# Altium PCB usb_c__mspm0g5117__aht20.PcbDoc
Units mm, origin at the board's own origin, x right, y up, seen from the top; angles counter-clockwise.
Board outline 92 x 60 mm, 2 copper layers (Top, Bottom), stack 0 mm thick; 36 components, 31 nets, 180 pads, 56 vias.
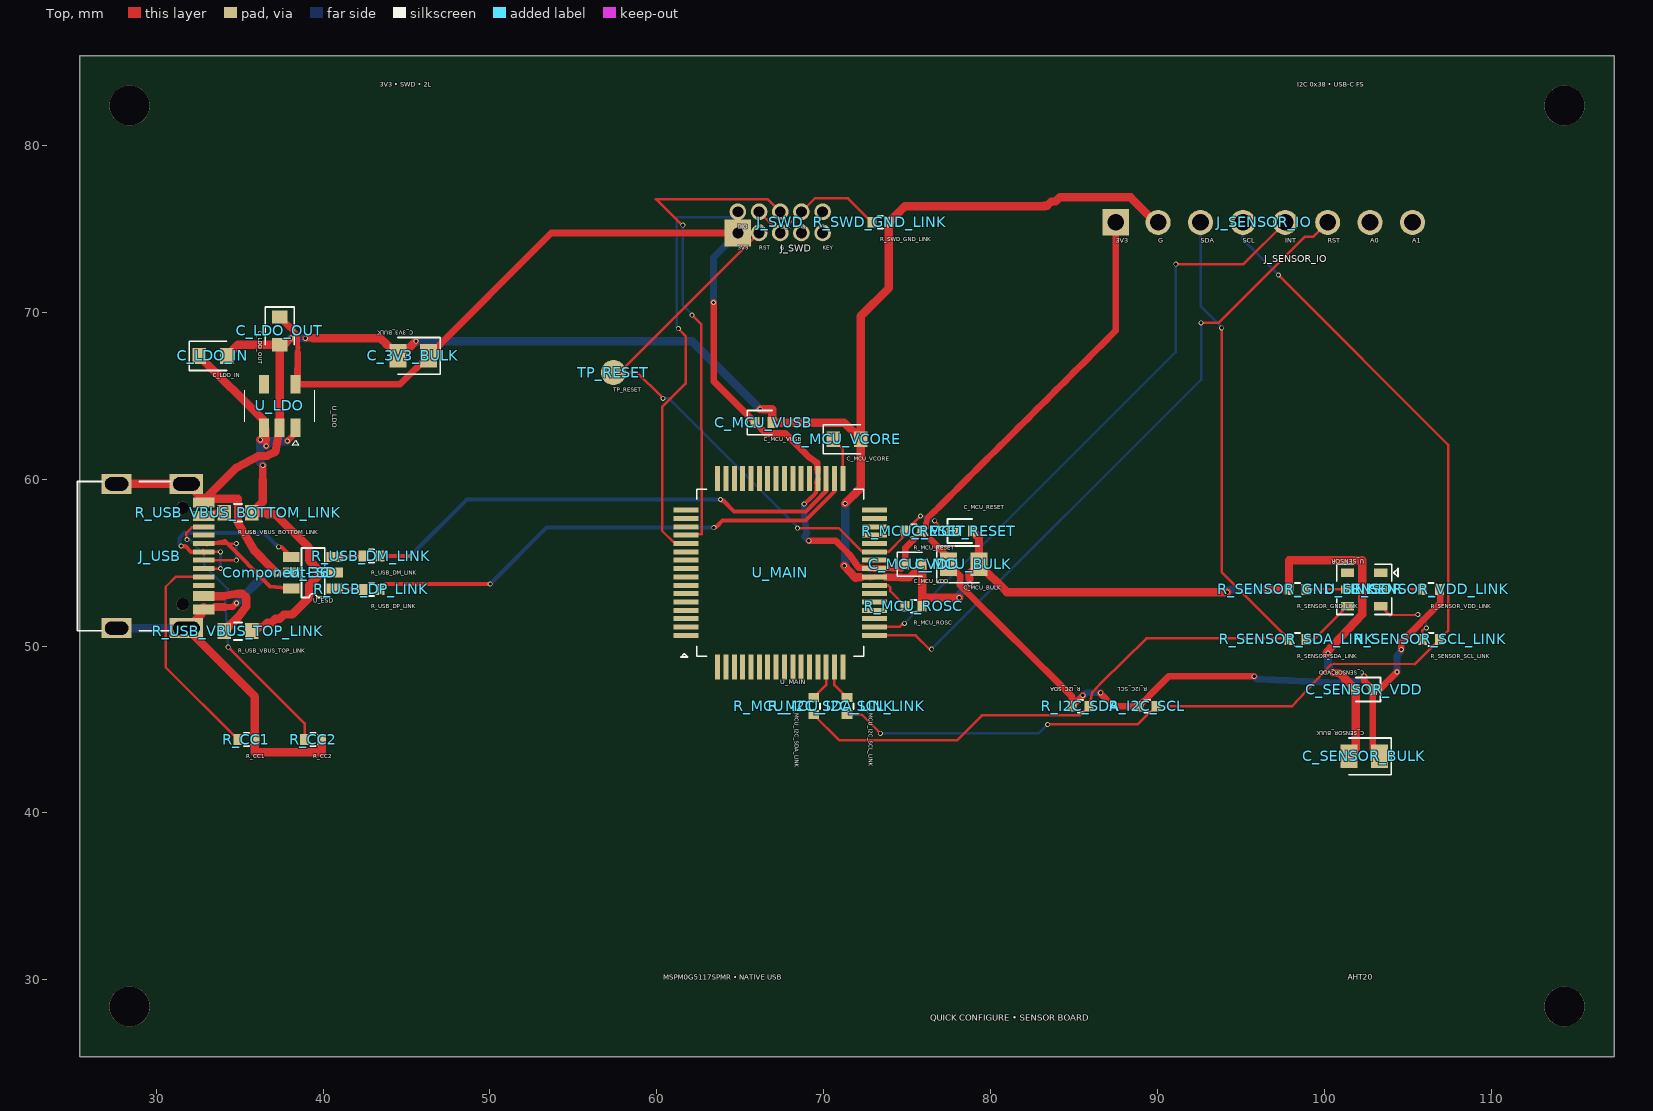
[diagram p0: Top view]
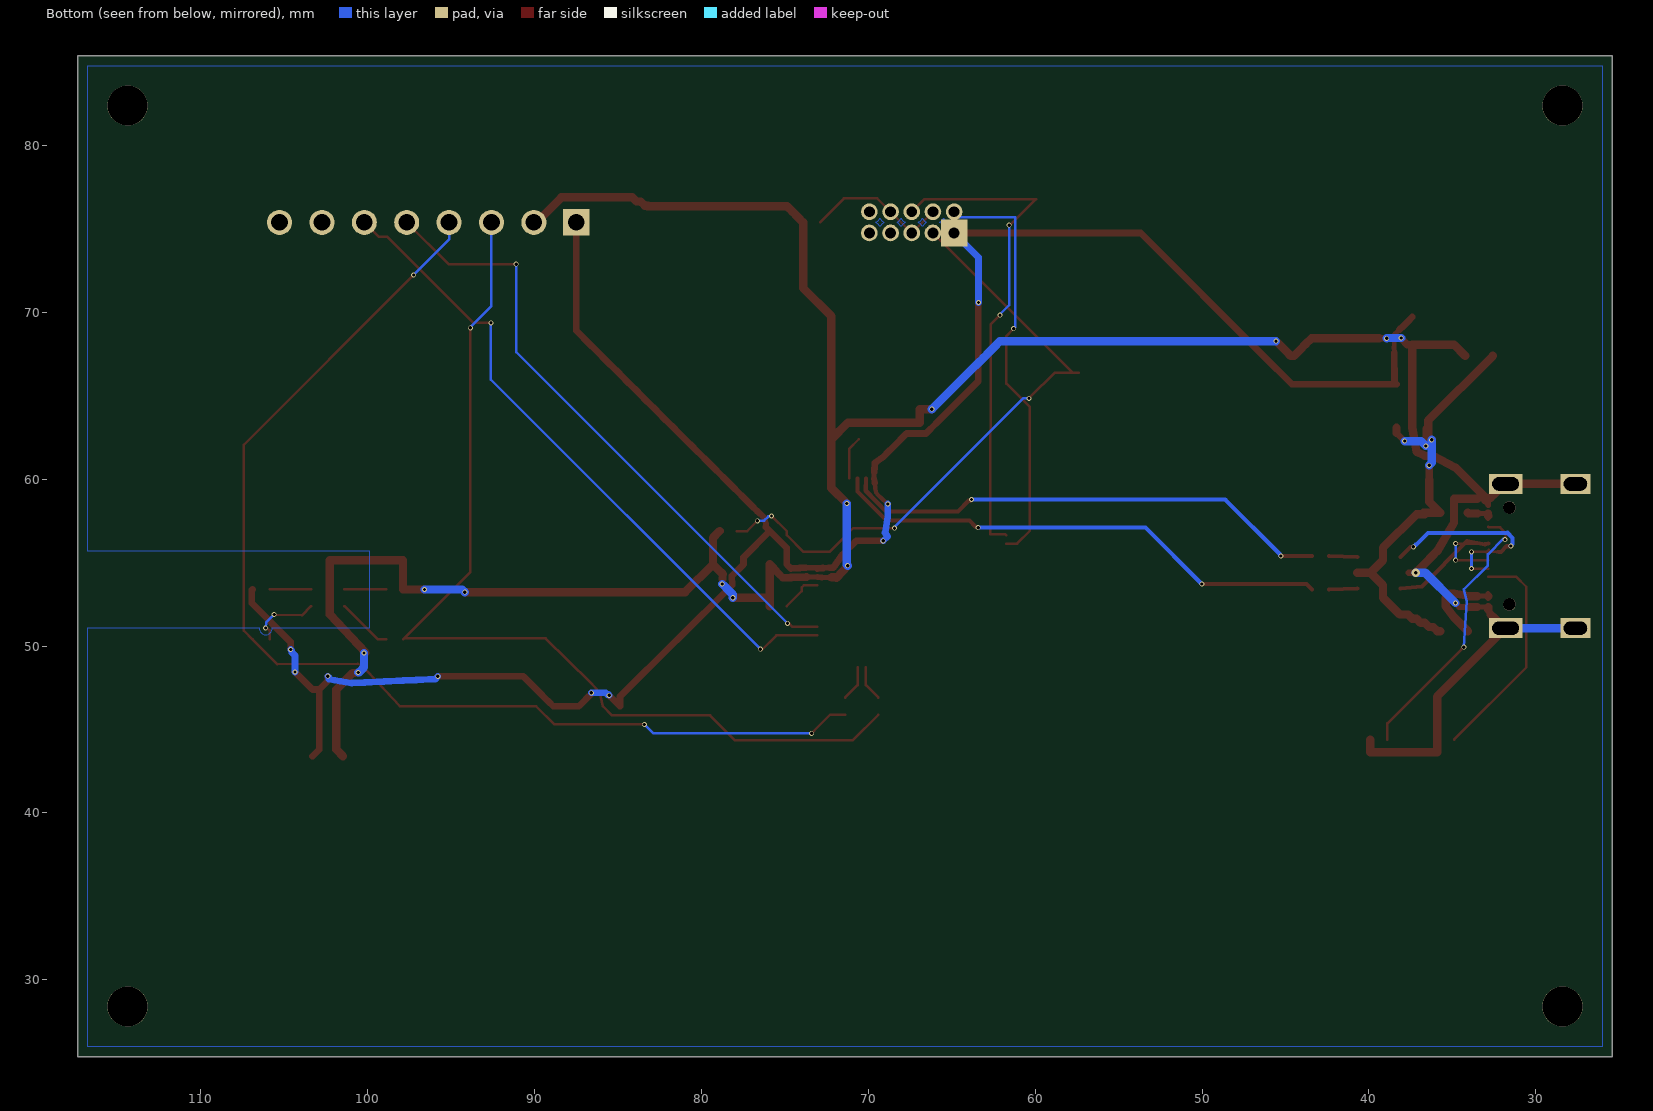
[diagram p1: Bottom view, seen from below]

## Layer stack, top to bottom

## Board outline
25.4,85.4 117.4,85.4 117.4,25.4 25.4,25.4

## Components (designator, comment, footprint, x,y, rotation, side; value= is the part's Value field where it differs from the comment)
C_3V3_BULK "" TSCIRCUIT-2.8500x1.4000mm 45.4,67.4 r180 top
C_LDO_IN "" TSCIRCUIT-2.4500x0.9500mm 33.4,67.4 r0 top
C_LDO_OUT "" TSCIRCUIT-0.9500x2.4500mm 37.4,68.9 r270 top
C_MCU_BULK "" TSCIRCUIT-2.8500x1.4000mm 78.4,54.9 r0 top
C_MCU_RESET "" TSCIRCUIT-1.5600x0.6400mm 78.4,56.9 r0 top
C_MCU_VCORE "" TSCIRCUIT-2.4500x0.9500mm 71.4,62.4 r0 top
C_MCU_VDD "" TSCIRCUIT-1.5600x0.6400mm 75.4,54.9 r0 top
C_MCU_VUSB "" TSCIRCUIT-1.5600x0.6400mm 66.4,63.4 r0 top
C_SENSOR_BULK "" TSCIRCUIT-2.8500x1.4000mm 102.4,43.4 r180 top
C_SENSOR_VDD "" TSCIRCUIT-1.5600x0.6400mm 102.4,47.4 r180 top
Component-36 "" TSCIRCUIT-0.5000x0.5000mm 37.2,54.4 r0 top
J_SENSOR_IO "" TSCIRCUIT-19.2800x1.5000mm 96.4,75.4 r0 top
J_SWD "" TSCIRCUIT-6.0800x2.2700mm 67.4,75.4 r0 top
J_USB "" TSCIRCUIT-6.7732x9.8502mm 30.113,55.4 r90 top
R_CC1 "" TSCIRCUIT-1.5600x0.6400mm 35.4,44.4 r0 top
R_CC2 "" TSCIRCUIT-1.5600x0.6400mm 39.4,44.4 r0 top
R_I2C_SCL "" TSCIRCUIT-1.5600x0.6400mm 89.4,46.4 r180 top
R_I2C_SDA "" TSCIRCUIT-1.5600x0.6400mm 85.4,46.4 r180 top
R_MCU_I2C_SCL_LINK "" TSCIRCUIT-0.6400x1.5600mm 71.4,46.4 r270 top
R_MCU_I2C_SDA_LINK "" TSCIRCUIT-0.6400x1.5600mm 69.4,46.4 r270 top
R_MCU_RESET "" TSCIRCUIT-1.5600x0.6400mm 75.4,56.9 r0 top
R_MCU_ROSC "" TSCIRCUIT-1.5600x0.6400mm 75.4,52.4 r0 top
R_SENSOR_GND_LINK "" TSCIRCUIT-1.5600x0.6400mm 98.4,53.4 r0 top
R_SENSOR_SCL_LINK "" TSCIRCUIT-1.5600x0.6400mm 106.4,50.4 r0 top
R_SENSOR_SDA_LINK "" TSCIRCUIT-1.5600x0.6400mm 98.4,50.4 r0 top
R_SENSOR_VDD_LINK "" TSCIRCUIT-1.5600x0.6400mm 106.4,53.4 r0 top
R_SWD_GND_LINK "" TSCIRCUIT-1.5600x0.6400mm 73.4,75.4 r0 top
R_USB_DM_LINK "" TSCIRCUIT-1.5600x0.6400mm 42.9,55.4 r0 top
R_USB_DP_LINK "" TSCIRCUIT-1.5600x0.6400mm 42.9,53.4 r0 top
R_USB_VBUS_BOTTOM_LINK "" TSCIRCUIT-2.4500x0.9500mm 34.9,58 r0 top
R_USB_VBUS_TOP_LINK "" TSCIRCUIT-2.4500x0.9500mm 34.9,50.9 r0 top
TP_RESET "" TSCIRCUIT-1.5000x1.5000mm 57.4,66.4 r0 top
U_ESD "" TSCIRCUIT-3.6000x2.5000mm 39.4,54.4 r0 top
U_LDO "" TSCIRCUIT-2.5000x3.7000mm 37.4,64.4 r270 top
U_MAIN "" TSCIRCUIT-12.8000x12.8000mm 67.4,54.4 r0 top
U_SENSOR "" TSCIRCUIT-2.8000x2.5000mm 102.4,53.4 r0 top

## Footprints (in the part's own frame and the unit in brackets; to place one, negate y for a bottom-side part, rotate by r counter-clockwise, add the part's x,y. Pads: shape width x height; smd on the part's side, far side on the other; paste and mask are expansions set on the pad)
TSCIRCUIT-0.5000x0.5000mm [mm]
TSCIRCUIT-0.6400x1.5600mm [mm]
  rect 0.54x0.64 smd: 1(-0.51,0) 2(0.51,0)
  silkscreen extent -0.15,-0.38 0.15,0.38
TSCIRCUIT-0.9500x2.4500mm [mm]
  rect 0.8x0.95 smd: 1(-0.825,0) 2(0.825,0)
  silkscreen extent -1.43,-0.87 0.82,0.88
TSCIRCUIT-1.5000x1.5000mm [mm]
  round 1.5 smd: 1(0,0)
TSCIRCUIT-1.5600x0.6400mm [mm]
  rect 0.54x0.64 smd: 1(-0.51,0) 2(0.51,0)
  silkscreen extent -0.98,-0.72 0.51,0.72
TSCIRCUIT-2.4500x0.9500mm [mm]
  rect 0.8x0.95 smd: 1(-0.825,0) 2(0.825,0)
  silkscreen extent -1.42,-0.87 0.82,0.87
TSCIRCUIT-2.5000x3.7000mm [mm]
  rect 1.1x0.6 smd: 1(1.3,0.95) 2(1.3,0) 3(1.3,-0.95) 4(-1.3,-0.95) 5(-1.3,0.95)
  silkscreen extent -0.95,-2.1 2.35,2.1
TSCIRCUIT-2.8000x2.5000mm [mm]
  rect 0.8x0.5 smd: 1(1,1) 2(1,0) 3(1,-1) 4(-1,-1) 5(-1,0) 6(-1,1)
  silkscreen extent -1.65,-1.5 2.02,1.5
TSCIRCUIT-2.8500x1.4000mm [mm]
  rect 1.025x1.4 smd: 1(-0.913,0) 2(0.913,0)
  silkscreen extent -1.63,-1.1 0.91,1.1
TSCIRCUIT-3.6000x2.5000mm [mm]
  rect 1x0.6 smd: 1(-1.3,-0.95) 2(-1.3,0) 3(-1.3,0.95) 4(1.3,0.95) 5(1.3,0) 6(1.3,-0.95)
  silkscreen extent -0.7,-1.49 0.7,1.49
TSCIRCUIT-6.0800x2.2700mm [mm]
  rect 1.6x1.6 hole 0.65: 1(-2.54,-0.635)
  round 1 hole 0.65: 2(-2.54,0.635) 3(-1.27,0.635) 4(0,0.635) 5(1.27,0.635) 6(2.54,0.635) 7(2.54,-0.635) 8(1.27,-0.635) 9(0,-0.635) 10(-1.27,-0.635)
TSCIRCUIT-6.7732x9.8502mm [mm]
  rect 0.3x1.3 smd: 1(-3.35,-2.737) 2(-3.05,-2.737) 3(-2.55,-2.737) 4(-2.25,-2.737) 5(-1.75,-2.737) 6(-1.25,-2.737) 7(-0.75,-2.737) 8(-0.25,-2.737) 9(0.25,-2.737) 10(0.75,-2.737) 11(1.25,-2.737) 12(1.75,-2.737) 13(2.55,-2.737) 14(2.25,-2.737) 15(3.35,-2.737) 16(3.05,-2.737)
  rect 1.2x2 hole 0.8 slot 1.6 at 90 deg: 17(-4.325,-1.693) 18(4.325,-1.693)
  rect 1.2x1.8 hole 0.8 slot 1.4 at 90 deg: 19(4.325,2.487) 20(-4.325,2.487)
  round 0.75 hole 0.75 unplated: NPTH-1(-2.9,-1.468) NPTH-2(2.9,-1.468)
  silkscreen extent -4.47,-0.75 4.47,4.83
TSCIRCUIT-12.8000x12.8000mm [mm]
  rect 1.5x0.3 smd: 1(-5.65,-3.75) 2(-5.65,-3.25) 3(-5.65,-2.75) 4(-5.65,-2.25) 5(-5.65,-1.75) 6(-5.65,-1.25) 7(-5.65,-0.75) 8(-5.65,-0.25) 9(-5.65,0.25) 10(-5.65,0.75) 11(-5.65,1.25) 12(-5.65,1.75) 13(-5.65,2.25) 14(-5.65,2.75) 15(-5.65,3.25) 16(-5.65,3.75) 33(5.65,3.75) 34(5.65,3.25) 35(5.65,2.75) 36(5.65,2.25) 37(5.65,1.75) 38(5.65,1.25) 39(5.65,0.75) 40(5.65,0.25) 41(5.65,-0.25) 42(5.65,-0.75) 43(5.65,-1.25) 44(5.65,-1.75) 45(5.65,-2.25) 46(5.65,-2.75) 47(5.65,-3.25) 48(5.65,-3.75)
  rect 0.3x1.5 smd: 17(-3.75,5.65) 18(-3.25,5.65) 19(-2.75,5.65) 20(-2.25,5.65) 21(-1.75,5.65) 22(-1.25,5.65) 23(-0.75,5.65) 24(-0.25,5.65) 25(0.25,5.65) 26(0.75,5.65) 27(1.25,5.65) 28(1.75,5.65) 29(2.25,5.65) 30(2.75,5.65) 31(3.25,5.65) 32(3.75,5.65) 49(3.75,-5.65) 50(3.25,-5.65) 51(2.75,-5.65) 52(2.25,-5.65) 53(1.75,-5.65) 54(1.25,-5.65) 55(0.75,-5.65) 56(0.25,-5.65) 57(-0.25,-5.65) 58(-0.75,-5.65) 59(-1.25,-5.65) 60(-1.75,-5.65) 61(-2.25,-5.65) 62(-2.75,-5.65) 63(-3.25,-5.65) 64(-3.75,-5.65)
  silkscreen extent -5.95,-5.05 5,5
TSCIRCUIT-19.2800x1.5000mm [mm]
  rect 1.6x1.6 hole 1: 1(-8.89,0)
  round 1.5 hole 1: 2(-6.35,0) 3(-3.81,0) 4(-1.27,0) 5(1.27,0) 6(3.81,0) 7(6.35,0) 8(8.89,0)

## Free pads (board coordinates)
  round 2.4 hole 2.4 unplated: NPTH-3(28.4,28.4) NPTH-4(114.4,28.4) NPTH-5(28.4,82.4) NPTH-6(114.4,82.4)

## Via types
v1: diameter 0.3, hole 0.2, Top to Bottom, 55 vias
v2: diameter 0.5, hole 0.2, Top to Bottom, 1 vias

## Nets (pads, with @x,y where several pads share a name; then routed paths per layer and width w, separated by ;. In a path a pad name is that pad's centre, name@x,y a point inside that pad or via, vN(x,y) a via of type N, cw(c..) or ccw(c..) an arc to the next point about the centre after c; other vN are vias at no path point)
".J_SWD > .pin2 to .U_MAIN > .pin12": J_SWD.2 U_MAIN.12 | length 25.1
  Top w0.15: v1(61.291,69.025) 61.314,69.002 61.727,68.589 61.728,65.735 60.322,64.324 60.317,56.917 61.083,56.147 U_MAIN.12
  Bottom w0.15: v1(61.291,69.025) 61.202,69.114 61.202,75.72 64.545,75.72 J_SWD.2
".J_SWD > .pin4 to .U_MAIN > .pin13": J_SWD.4 U_MAIN.13 | length 30
  Top w0.15: v1(61.557,75.228) 61.55,75.218 59.988,76.78 59.948,76.78 66.655,76.78 J_SWD.4 ; U_MAIN.13 61.819,56.719 62.692,56.719 62.676,69.272 v1(62.108,69.839)
  Bottom w0.15: v1(61.557,75.228) 61.557,70.437 62.069,69.925 62.069,69.878 v1(62.108,69.839)
".U_MAIN > .pin42 to .R_MCU_ROSC > .pin1": R_MCU_ROSC.1 U_MAIN.42 | length 2.5
  Top w0.15: U_MAIN.42 73.86,53.65 73.994,53.516 73.994,53.296 R_MCU_ROSC.1
AHT_GND_LOCAL: R_SENSOR_GND_LINK.2 U_SENSOR.5 | length 2.5
  Top w0.15: R_SENSOR_GND_LINK.2 U_SENSOR.5
AHT_SCL_LOCAL: R_SENSOR_SCL_LINK.1 U_SENSOR.3 | length 4.3
  Top w0.15: U_SENSOR.3 103.955,51.845 v1(105.613,51.897) ; R_SENSOR_SCL_LINK.1 105.89,50.946 106.034,51.09 v1(106.12,51.09)
  Bottom w0.15: v1(105.613,51.897) 105.758,51.752 105.763,51.752 106.077,51.438 v1(106.12,51.09)
AHT_SDA_LOCAL: R_SENSOR_SDA_LINK.2 U_SENSOR.4 | length 3.3
  Top w0.15: R_SENSOR_SDA_LINK.2 99.4,50.4 U_SENSOR.4
AHT_VDD_LOCAL: R_SENSOR_VDD_LINK.1 U_SENSOR.2 | length 2.5
  Top w0.15: U_SENSOR.2 R_SENSOR_VDD_LINK.1
GND: C_3V3_BULK.2 C_LDO_IN.2 C_LDO_OUT.2 C_MCU_BULK.2 C_MCU_RESET.2 C_MCU_VCORE.2 C_MCU_VDD.2 C_MCU_VUSB.2 C_SENSOR_BULK.2 C_SENSOR_VDD.2 J_SENSOR_IO.2 J_USB.1 J_USB.2 J_USB.15 J_USB.16 J_USB.17 J_USB.18 J_USB.19 J_USB.20 R_CC1.2 R_CC2.2 R_MCU_ROSC.2 R_SENSOR_GND_LINK.1 R_SWD_GND_LINK.2 U_ESD.2 U_LDO.2 U_MAIN.41 | length 187.8
  Top w0.275: J_USB.16 J_USB.15@33.04,58.641
  Top w0.3: J_USB.1@32.699,51.9 J_USB.1 J_USB.1@32.849,52.2 ; J_USB.15@32.699,58.9 J_USB.15 ; J_USB.2 J_USB.2@32.946,52.332 ; J_USB.16@32.849,58.6 J_USB.15 ; J_USB.15@32.999,58.9 J_USB.15 ; J_USB.2@33.037,52.35 33.13,52.35 33.224,52.35 33.318,52.35 33.412,52.35 J_USB.2@33.499,52.35 ; J_USB.15@33.04,58.641 33.231,58.832 33.499,58.832 ; 72.3,54.12 72.425,54.12 72.55,54.12 72.675,54.12 U_MAIN.41@72.796,54.111 ; U_MAIN.41 73.144,54.15 73.237,54.15 73.331,54.15 73.425,54.15 73.519,54.15 73.612,54.15 U_MAIN.41@73.706,54.15
  Top w0.301: J_USB.2@32.946,52.332 J_USB.2@33.037,52.35
  Top w0.325: J_USB.16 J_USB.16@32.849,58.6
  Top w0.35: v1@38.017,68.396 v1(38.068,68.474) ; 78.744,54.022 v1(78.76,53.729)
  Top w0.375: 34.091,52.35 34.584,52.35 v1(34.805,52.583) ; 45.429,68.145 45.435,68.145 v1(45.568,68.278) ; U_MAIN.41@72.796,54.111 U_MAIN.41
  Top w0.4: 37.2,54.4 U_ESD.2@37.6,54.4 ; v1(38.933,68.451) 39.383,68.451 ; 72.175,54.12 72.3,54.12
  Top w0.437: 75.119,54.087 75.337,54.306 75.556,54.525
  Top w0.45: C_LDO_OUT.2 37.696,68.075 v1@38.017,68.396 ; 74.648,54.108 75.119,54.087
  Top w0.475: U_MAIN.41@73.706,54.15 74.177,54.129 74.648,54.108 ; 78.727,54.314 78.744,54.022
  Top w0.5: J_USB.19 J_USB.18 31.874,59.725 32.474,59.125 32.699,58.9 ; 32.699,51.9 32.474,51.675 31.874,51.075 J_USB.17 35.91,46.971 R_CC1.2 35.91,43.65 39.91,43.65 R_CC2.2 ; J_USB.1@32.849,52.2 J_USB.2 ; 32.999,58.9 34.803,60.704 34.805,60.704 36.15,61.4 36.65,61.4 37.15,61.65 U_LDO.2 C_LDO_OUT.2 34.9,68.075 C_LDO_IN.2 ; 33.499,52.35 33.505,52.35 33.599,52.35 34.091,52.35 ; 33.499,58.832 34.9,58.832 34.9,57.4 35.909,55.691 36.232,55.368 36.555,55.045 36.877,54.723 37.2,54.4 ; 39.383,68.451 39.834,68.451 40.284,68.451 40.734,68.451 41.185,68.451 41.635,68.451 42.085,68.451 42.536,68.451 42.986,68.451 43.436,68.451 43.787,68.101 44.137,67.75 C_3V3_BULK.2 44.684,67.4 44.932,67.648 45.181,67.897 45.429,68.145 ; v1(66.2,64.2) 66.91,64.2 C_MCU_VUSB.2 71.225,63.4 C_MCU_VCORE.2 ; v1(71.237,54.819) 71.913,54.09 72.05,54.12 72.175,54.12 ; v1(71.292,58.547) 72.225,59.48 C_MCU_VCORE.2 ; 75.556,54.525 75.66,54.65 C_MCU_VDD.2 ; R_MCU_ROSC.2 C_MCU_VDD.2 ; v1(78.127,52.901) 75.91,52.901 C_MCU_VDD.2 ; 78.727,54.314 79.02,54.607 C_MCU_BULK.2 ; C_MCU_RESET.2 79.313,56.497 C_MCU_BULK.2 ; 80.98,53.233 C_MCU_BULK.2 ; 80.98,53.233 v1(94.183,53.233) ; J_SENSOR_IO.2 89.9,75.4 88.4,76.9 84.15,76.9 83.9,76.65 83.65,76.65 83.4,76.4 83.202,76.4 83.235,76.366 82.748,76.366 82.261,76.366 81.773,76.366 81.286,76.366 80.799,76.366 80.311,76.366 79.824,76.366 79.337,76.366 78.849,76.366 78.362,76.366 77.875,76.366 77.387,76.366 76.9,76.366 76.413,76.366 75.925,76.366 75.438,76.366 74.951,76.366 74.876,76.366 74.554,76.044 74.232,75.722 R_SWD_GND_LINK.2 73.91,71.464 72.225,69.779 72.225,69.287 72.225,68.795 72.225,68.303 72.225,67.812 72.225,67.32 72.225,66.828 72.225,66.336 72.225,65.844 72.225,65.352 72.225,64.86 72.225,64.368 72.225,63.876 72.225,63.384 72.225,62.892 C_MCU_VCORE.2 ; v1(96.6,53.4) 96.64,53.4 R_SENSOR_GND_LINK.1 97.89,55.15 102.275,55.15 102.275,51.9 100.137,49.611 100.206,49.611 v1(100.231,49.586) ; v1(100.579,48.419) 100.912,48.378 101.238,48.052 101.564,47.726 C_SENSOR_VDD.2 101.89,43.803 C_SENSOR_BULK.2
  Bottom w0.5: J_USB.20 J_USB.17 ; v1(34.805,52.583) 36.622,54.4 37.2,54.4 ; v1(38.068,68.474) 38.91,68.474 v1(38.933,68.451) ; v1(45.568,68.278) 46.055,68.278 46.542,68.278 47.028,68.278 47.515,68.278 48.002,68.278 48.489,68.278 48.975,68.278 49.462,68.278 49.949,68.278 50.436,68.278 50.923,68.278 51.409,68.278 51.896,68.278 52.383,68.278 52.87,68.278 53.356,68.278 53.843,68.278 54.33,68.278 54.817,68.278 55.304,68.278 55.79,68.278 56.277,68.278 56.764,68.278 57.251,68.278 57.737,68.278 58.224,68.278 58.711,68.278 59.198,68.278 59.685,68.278 60.171,68.278 60.658,68.278 61.145,68.278 61.632,68.278 62.118,68.278 62.45,67.947 62.781,67.615 63.113,67.284 63.444,66.952 63.776,66.621 64.107,66.289 64.438,65.958 64.77,65.627 65.101,65.295 65.433,64.964 65.764,64.632 66.096,64.301 66.099,64.301 v1(66.2,64.2) ; v1(71.237,54.819) 71.292,54.875 v1(71.292,58.547) ; v1(78.127,52.901) 78.127,53.096 78.411,53.38 v1@78.696,53.664 ; v1@78.696,53.665 v1(78.76,53.729) ; v1(94.183,53.233) 94.35,53.4 v1(96.6,53.4) ; v1(100.231,49.586) 100.231,49.161 100.231,48.736 100.513,48.455 100.513,48.442 v1(100.579,48.419)
MAIN_RESET: C_MCU_RESET.1 J_SWD.10 R_MCU_RESET.1 TP_RESET.1 U_MAIN.38 | length 38.6
  Top w0.15: v1(60.37,64.855) 60.302,64.923 58.825,66.4 TP_RESET.1 57.765,66.4 J_SWD.10 ; v1(68.434,57.074) 70.905,57.074 72.311,55.669 73.031,55.669 U_MAIN.38 73.889,55.65 74.889,56.651 R_MCU_RESET.1@74.889,56.899 ; R_MCU_RESET.1 75.795,57.805 v1(75.807,57.805) ; v1(76.65,57.509) 76.645,57.514 77.259,56.9 C_MCU_RESET.1
  Bottom w0.15: v1(60.37,64.855) 60.727,64.85 68.401,57.176 68.401,57.107 v1(68.434,57.074) ; v1(75.807,57.805) 75.833,57.779 75.995,57.779 76.252,57.522 v1(76.65,57.509)
MCU_I2C_SCL_LOCAL: R_MCU_I2C_SCL_LINK.1 U_MAIN.50 | length 2.2
  Top w0.15: U_MAIN.50 70.65,47.66 R_MCU_I2C_SCL_LINK.1
MCU_I2C_SDA_LOCAL: R_MCU_I2C_SDA_LINK.1 U_MAIN.51 | length 2.2
  Top w0.15: R_MCU_I2C_SDA_LINK.1 70.15,47.66 U_MAIN.51
MSPM0_VCORE: C_MCU_VCORE.1 U_MAIN.32 | length 2.6
  Top w0.15: C_MCU_VCORE.1 71.15,61.825 U_MAIN.32
SENSOR_ADDR0: J_SENSOR_IO.7
SENSOR_ADDR1: J_SENSOR_IO.8
SENSOR_INT: J_SENSOR_IO.5 U_MAIN.47 | length 37.7
  Top w0.15: U_MAIN.47 74.548,51.15 74.726,51.328 74.804,51.328 v1(74.847,51.371) ; v1(91.113,72.894) 95.164,72.894 J_SENSOR_IO.5
  Bottom w0.15: v1(74.847,51.371) 91.104,67.628 91.104,72.885 v1(91.113,72.894)
SENSOR_RESET: J_SENSOR_IO.6 U_MAIN.48 | length 40.2
  Top w0.15: U_MAIN.48 75.516,50.65 76.422,49.745 76.422,49.77 v1(76.472,49.82) ; v1(92.622,69.379) 93.667,69.379 98.822,74.533 99.343,74.533 J_SENSOR_IO.6
  Bottom w0.15: v1(76.472,49.82) 92.621,65.969 v1@92.621,69.378
SENSOR_SCL: J_SENSOR_IO.4 R_I2C_SCL.1 R_MCU_I2C_SCL_LINK.2 R_SENSOR_SCL_LINK.2 | length 68.7
  Top w0.15: R_MCU_I2C_SCL_LINK.2 72.292,45.89 73.252,44.93 73.252,44.92 v1(73.4,44.772) ; v1(83.426,45.306) 88.816,45.306 R_I2C_SCL.1 98.083,46.4 100.421,48.892 100.61,48.931 105.439,48.929 R_SENSOR_SCL_LINK.2 107.44,50.93 107.44,62.065 v1(97.255,72.25)
  Bottom w0.15: v1(73.4,44.772) 82.874,44.772 83.417,45.315 v1(83.426,45.306) ; J_SENSOR_IO.4 95.13,74.375 97.233,72.272 v1(97.255,72.25)
SENSOR_SDA: J_SENSOR_IO.3 R_I2C_SDA.1 R_MCU_I2C_SDA_LINK.2 R_SENSOR_SDA_LINK.1 | length 59.2
  Top w0.15: R_MCU_I2C_SDA_LINK.2 70.94,44.35 77.987,44.35 79.49,45.853 85.363,45.853 R_I2C_SDA.1 86.099,47.224 86.665,47.825 89.346,50.46 97.83,50.46 R_SENSOR_SDA_LINK.1 93.855,54.435 v1(93.855,69.076)
  Bottom w0.15: J_SENSOR_IO.3 92.59,70.381 93.814,69.157 93.814,69.117 v1(93.855,69.076)
swd-ground-1-to-2: J_SWD.3 J_SWD.5 J_SWD.9 R_SWD_GND_LINK.1 | length 8.8
  Top w0.15: J_SWD.3 J_SWD.9 J_SWD.5 69.481,76.846 71.471,76.846 71.471,76.819 R_SWD_GND_LINK.1
usb-dm-device: R_USB_DM_LINK.1 U_ESD.4 | length 1.7
  Top w0.25: U_ESD.4 R_USB_DM_LINK.1
usb-dm-mcu: R_USB_DM_LINK.2 U_MAIN.30 | length 29.8
  Top w0.25: R_USB_DM_LINK.2 v1(45.28,55.4) ; v1(63.815,58.794) 63.897,58.712 63.993,58.712 64.637,58.068 68.916,58.052 70.153,59.315 U_MAIN.30
  Bottom w0.25: v1(45.28,55.4) 45.325,55.445 45.325,55.506 48.613,58.794 v1(63.815,58.794)
usb-dm-port-tie: J_USB.7 J_USB.9 U_ESD.3 | length 13.2
  Top w0.15: J_USB.9@32.349,55.65 32.38,55.65 32.474,55.65 32.568,55.65 32.662,55.65 32.755,55.65 32.825,55.765 32.989,55.65 32.849,55.51 32.709,55.65 J_USB.9 v1(33.85,55.65) ; J_USB.7 v1(33.85,54.65)
  Top w0.175: J_USB.9@32.287,55.65 J_USB.9@32.349,55.65
  Top w0.212: 32.193,55.65 J_USB.9@32.287,55.65
  Top w0.25: v1(31.496,56) 31.526,55.993 31.741,55.993 32.084,55.65 32.099,55.65 32.193,55.65 ; v1(37.337,55.95) 37.5,55.95 U_ESD.3
  Bottom w0.15: v1(33.85,54.65) v1(33.85,55.65)
  Bottom w0.25: v1(31.496,56) 31.4,56.119 31.388,56.481 31.697,56.798 36.465,56.782 37.172,56.075 37.212,56.075 v1(37.337,55.95)
usb-dp-device: R_USB_DP_LINK.1 U_ESD.6 | length 1.7
  Top w0.25: U_ESD.6 R_USB_DP_LINK.1
usb-dp-mcu: R_USB_DP_LINK.2 U_MAIN.31 | length 30.5
  Top w0.25: R_USB_DP_LINK.2 43.738,53.728 v1(50.013,53.728) ; v1(63.418,57.105) 63.46,57.147 63.561,57.147 63.938,57.524 68.904,57.523 70.65,59.27 U_MAIN.31
  Bottom w0.25: v1(50.013,53.728) 50.054,53.769 53.39,57.105 v1(63.418,57.105)
usb-dp-port-tie: J_USB.8 J_USB.10 U_ESD.1 | length 11.3
  Top w0.15: J_USB.8 v1(34.8,55.15) ; J_USB.10 v1(34.8,56.15)
  Top w0.25: J_USB.10 33.039,56.103 34.124,56.304 36.808,53.566 U_ESD.1
  Bottom w0.15: v1(34.8,55.15) v1(34.8,56.15)
USB_CC1: J_USB.6 R_CC1.1 | length 13.5
  Top w0.15: J_USB.6 31.161,54.15 30.569,53.558 30.569,48.721 R_CC1.1
USB_CC2: J_USB.12 R_CC2.1 | length 16.7
  Top w0.15: v1(31.839,56.384) 31.8,56.788 32.13,57.118 32.817,57.118 J_USB.12 ; v1(34.308,49.942) 34.439,49.811 34.45,49.811 38.89,45.371 R_CC2.1
  Bottom w0.15: v1(31.839,56.384) 31.85,56.45 31.92,56.45 32.871,55.499 32.871,54.845 34.308,53.409 34.147,52.702 v1(34.308,49.942)
USB_VBUS_BOTTOM_LOCAL: J_USB.13 J_USB.14 R_USB_VBUS_BOTTOM_LINK.1 | length 1.5
  Top w0.3: J_USB.14 J_USB.14@32.849,57.8 ; J_USB.13 32.927,57.95 33.005,57.95 33.083,57.95 33.161,57.95 33.239,57.95 33.317,57.95 33.394,57.95 33.472,57.95 33.499,57.95
  Top w0.475: J_USB.13@32.849,57.8 J_USB.13 ; 33.499,57.95 R_USB_VBUS_BOTTOM_LINK.1@33.762,57.95
  Top w0.5: R_USB_VBUS_BOTTOM_LINK.1@33.762,57.95 34.025,57.95 R_USB_VBUS_BOTTOM_LINK.1
USB_VBUS_TOP_LOCAL: J_USB.3 J_USB.4 R_USB_VBUS_TOP_LINK.1 | length 5.5
  Top w0.275: J_USB.3 J_USB.3@32.999,53
  Top w0.3: J_USB.3 32.849,53 J_USB.4 ; J_USB.3@32.999,53 33.036,53 33.499,53
  Top w0.5: 33.499,53 33.521,53 34.006,53 34.9,53.15 35.15,53.15 35.4,52.9 35.4,52.4 34.884,51.706 34.614,51.437 34.345,51.169 R_USB_VBUS_TOP_LINK.1
VBUS5: C_LDO_IN.1 R_USB_VBUS_BOTTOM_LINK.2 R_USB_VBUS_TOP_LINK.2 U_ESD.5 U_LDO.1 U_LDO.3 | length 28.9
  Top w0.375: v1(37.854,62.291) 38.124,62.553 U_LDO.1@38.35,62.779
  Top w0.4: 36.554,62.346 v1(36.583,61.993)
  Top w0.425: 36.384,59.964 36.384,60.399 v1(36.384,60.834)
  Top w0.5: C_LDO_IN.1 36.45,63.525 U_LDO.3 ; R_USB_VBUS_TOP_LINK.2 35.9,50.9 36.15,51.15 36.4,51.15 36.65,51.4 36.9,51.4 37.15,51.65 37.4,51.65 37.65,51.9 38.15,51.9 39.15,52.9 39.15,53.65 39.9,54.4 ; v1(36.234,62.362) 36.45,62.578 U_LDO.3 ; 36.384,59.964 36.384,59.529 36.384,59.094 36.384,58.659 36.054,58.329 R_USB_VBUS_BOTTOM_LINK.2 36.225,58 36.725,58 36.65,57.925 36.65,57.9 37.15,57.9 39.15,55.9 39.15,55.15 39.9,54.4 ; 36.554,62.346 36.526,62.699 36.526,63.024 U_LDO.3 ; U_LDO.1@38.35,62.779 U_LDO.1 ; 39.9,54.4 U_ESD.5 39.9,54.4
  Bottom w0.5: v1(36.234,62.362) 36.234,60.984 v1(36.384,60.834) ; v1(36.583,61.993) 36.881,62.291 v1(37.854,62.291)
VCC_3V3: C_3V3_BULK.1 C_LDO_OUT.1 C_MCU_BULK.1 C_MCU_VDD.1 C_MCU_VUSB.1 C_SENSOR_BULK.1 C_SENSOR_VDD.1 J_SENSOR_IO.1 J_SWD.1 R_I2C_SCL.2 R_I2C_SDA.2 R_MCU_RESET.2 R_SENSOR_VDD_LINK.2 U_LDO.5 U_MAIN.29 U_MAIN.40 | length 138.6
  Top w0.25: v1(68.829,58.52) 68.952,58.602 69.184,58.834 69.417,59.067 69.55,59.2 69.583,59.483 U_MAIN.29@69.617,59.767
  Top w0.275: 38.48,67.943 38.483,68.298 38.486,68.654
  Top w0.3: 38.166,68.973 38.4,68.75 38.464,68.666 38.486,68.654 ; 38.478,67.588 38.48,67.943 ; U_MAIN.29 U_MAIN.29@69.65,60.425 ; 72.3,54.689 U_MAIN.40
  Top w0.332: U_MAIN.40@73.797,54.692 U_MAIN.40@73.8,54.692
  Top w0.335: U_MAIN.40@72.374,54.705 72.729,54.717 73.075,54.709 73.422,54.701 U_MAIN.40@73.768,54.693
  Top w0.349: U_MAIN.40@72.374,54.705 U_MAIN.40@72.712,54.678
  Top w0.35: R_MCU_RESET.2@76.149,57.139 76.142,57.351 76.212,57.675 76.388,57.85 76.539,57.984
  Top w0.363: U_MAIN.29@69.617,59.767 U_MAIN.29
  Top w0.387: U_MAIN.40@72.712,54.678 U_MAIN.40
  Top w0.4: C_LDO_OUT.1 37.666,69.46 37.932,69.195 38.166,68.973 ; 38.478,67.588 38.475,67.233 38.472,66.877 38.469,66.522 38.466,66.167 38.463,65.811 U_LDO.5 44.613,65.7 C_3V3_BULK.1 53.678,74.76 J_SWD.1 ; v1(63.4,70.6) 63.404,70.596 63.404,65.886 C_MCU_VUSB.1 66.109,63.181 66.327,62.963 66.546,62.744 66.932,62.744 67.319,62.744 67.706,62.744 67.983,62.467 68.261,62.189 68.539,61.911 68.817,61.633 69.094,61.356 69.6,61 U_MAIN.29@69.65,60.425 ; v1(69.116,56.311) 69.44,56.311 69.763,56.311 70.087,56.31 70.41,56.31 70.734,56.31 70.998,56.043 71.263,55.776 71.528,55.509 72.1,54.7 72.3,54.689 ; U_MAIN.40@73.768,54.693 74.115,54.685 73.8,54.692 ; U_MAIN.40@73.797,54.692 74.64,54.65 C_MCU_VDD.1 74.89,55.88 R_MCU_RESET.2 ; R_MCU_RESET.2@76.149,57.139 R_MCU_RESET.2 ; 76.539,57.984 76.691,58.117 76.968,58.394 77.245,58.671 77.523,58.948 77.8,59.224 78.078,59.501 78.355,59.778 78.632,60.055 78.91,60.332 79.187,60.608 79.465,60.885 79.742,61.162 80.02,61.439 80.297,61.716 80.574,61.992 80.852,62.269 81.129,62.546 81.407,62.823 81.684,63.099 81.961,63.376 82.239,63.653 82.516,63.93 82.794,64.207 83.071,64.483 83.348,64.76 83.626,65.037 83.903,65.314 84.181,65.591 84.458,65.867 84.736,66.144 85.013,66.421 85.29,66.698 85.568,66.975 85.845,67.251 86.123,67.528 86.4,67.805 86.677,68.082 86.955,68.358 87.232,68.635 87.51,68.912 87.51,69.294 87.51,69.675 87.51,70.057 87.51,70.439 87.51,70.82 87.51,71.202 87.51,71.584 87.51,71.965 87.51,72.347 87.51,72.728 87.51,73.11 87.51,73.492 87.51,73.873 87.51,74.255 87.51,74.637 87.51,75.018 J_SENSOR_IO.1 ; v1(85.537,47.055) 85.537,47.047 85.321,46.831 85.106,46.616 R_I2C_SDA.2 84.889,46.985 78.154,53.658 78.186,54.201 C_MCU_BULK.1 77.488,55.323 R_MCU_RESET.2 ; v1(86.6,47.2) 86.575,47.175 86.834,46.917 87.092,46.658 87.351,46.4 87.735,46.4 88.12,46.4 88.505,46.4 R_I2C_SCL.2 89.146,46.656 89.401,46.911 89.657,47.167 89.913,47.423 90.168,47.678 90.424,47.934 90.68,48.19 91.062,48.19 91.444,48.19 91.826,48.19 92.209,48.19 92.591,48.19 92.973,48.19 93.355,48.19 93.737,48.19 94.12,48.19 94.502,48.19 94.884,48.19 95.266,48.19 95.649,48.19 v1@95.8,48.19 ; v1(102.4,48.2) 102.4,47.91 102.655,47.655 C_SENSOR_VDD.1 ; C_SENSOR_BULK.1 102.91,43.803 C_SENSOR_VDD.1 ; v1(104.367,48.454) 104.267,48.354 104.265,48.354 103.311,47.4 C_SENSOR_VDD.1 ; v1(104.625,49.8) 104.626,50.26 106.957,52.577 106.949,53.361 R_SENSOR_VDD_LINK.2
  Bottom w0.4: v1(63.4,70.6) 63.4,73.305 J_SWD.1 ; v1(68.829,58.52) 68.834,58.132 68.838,57.743 69,56.8 68.85,56.577 69.079,56.348 v1(69.116,56.311) ; v1(85.537,47.055) 85.581,47.099 85.643,47.099 85.744,47.2 86.03,47.2 86.315,47.2 v1(86.6,47.2) ; v1(95.8,48.19) 95.948,48.03 96.333,48.012 96.718,47.993 97.104,47.974 97.489,47.955 97.874,47.937 98.26,47.918 98.645,47.899 99.03,47.88 99.416,47.862 99.801,47.843 100.186,47.824 100.572,47.806 100.957,47.787 101.299,47.843 101.64,47.899 101.982,47.955 102.324,48.011 102.324,48.124 v1(102.4,48.2) ; v1(104.367,48.454) 104.367,49.436 104.556,49.625 104.556,49.731 v1(104.625,49.8)
pads on no net: J_SWD.6 J_SWD.7 J_SWD.8 J_USB.5 J_USB.11 J_USB.NPTH-1 J_USB.NPTH-2 U_LDO.4 U_MAIN.1 U_MAIN.2 U_MAIN.3 U_MAIN.4 U_MAIN.5 U_MAIN.6 U_MAIN.7 U_MAIN.8 U_MAIN.9 U_MAIN.10 U_MAIN.11 U_MAIN.14 U_MAIN.15 U_MAIN.16 U_MAIN.17 U_MAIN.18 U_MAIN.19 U_MAIN.20 U_MAIN.21 U_MAIN.22 U_MAIN.23 U_MAIN.24 U_MAIN.25 U_MAIN.26 U_MAIN.27 U_MAIN.28 U_MAIN.33 U_MAIN.34 U_MAIN.35 U_MAIN.36 U_MAIN.37 U_MAIN.39 U_MAIN.43 U_MAIN.44 U_MAIN.45 U_MAIN.46 U_MAIN.49 U_MAIN.52 U_MAIN.53 U_MAIN.54 U_MAIN.55 U_MAIN.56 U_MAIN.57 U_MAIN.58 U_MAIN.59 U_MAIN.60 U_MAIN.61 U_MAIN.62 U_MAIN.63 U_MAIN.64 U_SENSOR.1 U_SENSOR.6
copper on no net:
  other v2: 37.2,54.4

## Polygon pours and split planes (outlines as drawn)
GND on Bottom (solid): 116.8,84.8 26,84.8 26,26 116.8,26 116.8,51.1 106.519,51.1 106.52,51.09 106.513,51.012 106.49,50.937 106.453,50.867 106.403,50.807 106.342,50.757 106.273,50.72 106.198,50.697 106.12,50.69 106.042,50.697 105.967,50.72 105.898,50.757 105.837,50.807 105.788,50.867 105.751,50.937 105.728,51.012 105.72,51.09 105.721,51.1 100.2,51.1 99.9,51.1 99.9,51.4 99.9,55.1 99.9,55.7 100.5,55.7 116.8,55.7
GND on Bottom (solid): 65.495,75.64 65.484,75.618 65.399,75.515 65.591,75.515 65.506,75.618
GND on Bottom (solid): 65.61,75.496 65.61,75.304 65.713,75.389 65.735,75.4 65.713,75.411
GND on Bottom (solid): 69.305,75.64 69.294,75.618 69.2,75.505 69.087,75.411 69.065,75.4 69.087,75.389 69.2,75.295 69.294,75.182 69.305,75.16 69.316,75.182 69.41,75.295 69.523,75.389 69.545,75.4 69.523,75.411 69.41,75.505 69.316,75.618
GND on Bottom (solid): 68.035,75.64 68.024,75.618 67.93,75.505 67.817,75.411 67.795,75.4 67.817,75.389 67.93,75.295 68.024,75.182 68.035,75.16 68.046,75.182 68.14,75.295 68.253,75.389 68.275,75.4 68.253,75.411 68.14,75.505 68.046,75.618
GND on Bottom (solid): 66.765,75.64 66.754,75.618 66.66,75.505 66.547,75.411 66.525,75.4 66.547,75.389 66.66,75.295 66.754,75.182 66.765,75.16 66.776,75.182 66.87,75.295 66.983,75.389 67.005,75.4 66.983,75.411 66.87,75.505 66.776,75.618

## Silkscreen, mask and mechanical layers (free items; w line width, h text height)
Top Overlay:
  text "3V3 • SWD • 2L" at 43.4,83.4 h0.48
  text "I2C 0x38 • USB-C FS" at 98.4,83.4 h0.5
  text "MSPM0G5117SPMR • NATIVE USB" at 60.4,29.9 h0.52
  text "AHT20" at 101.4,29.9 h0.55
  text "QUICK CONFIGURE • SENSOR BOARD" at 76.4,27.4 h0.65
